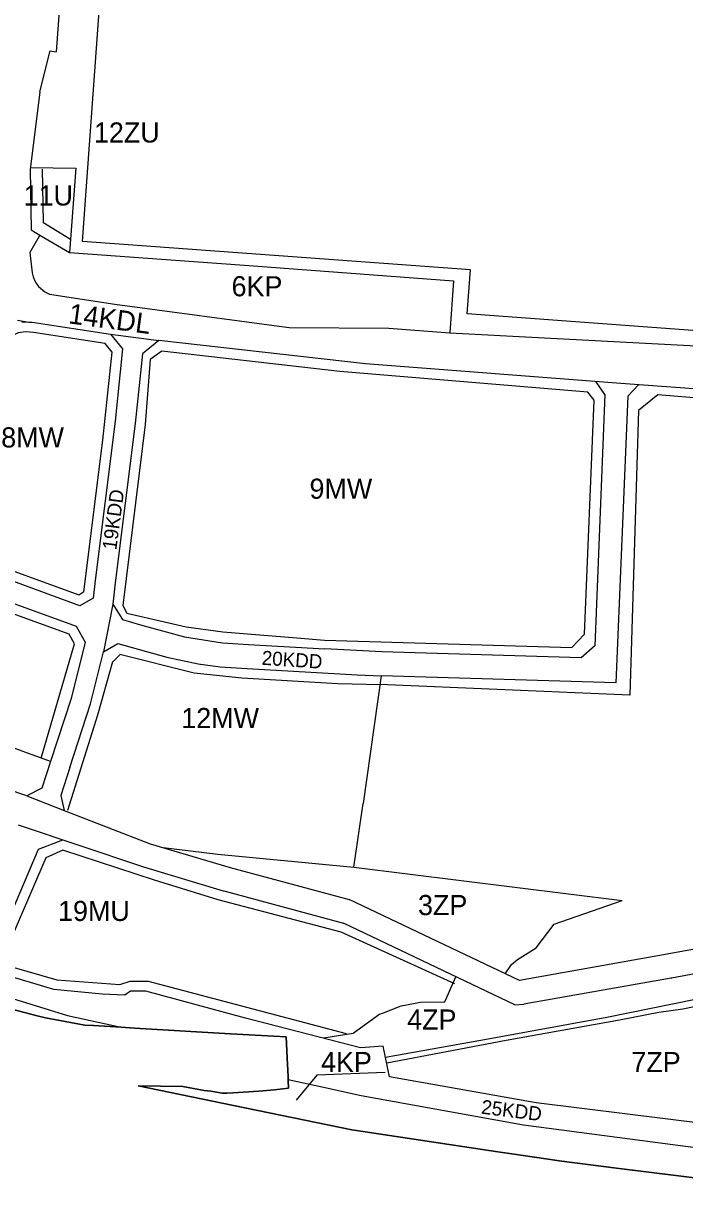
# Model space of a CAD drawing. Extents: x 7428203 to 7432868, y 5542672 to 5545406.
# Drawn here: x 7432004 to 7432333, y 5542818 to 5543396 of the extents above; entities that cross this region are included whole.
import ezdxf

# ---------------------------------------------------------------- set-up
doc = ezdxf.new("R2010")
doc.units = 0
for name, color, linetype in [('__LEGENDA_RAMKA_LOGO_PODZIAŁKA', 7, 'Continuous'), ('_GRANICA_MIASTA', 7, 'Continuous'), ('granicaBulwary', 7, 'Continuous'), ('MPZP_uchwalone_nieobowiazujace jeszcze_SZRAF', 7, 'Continuous')]:
    doc.layers.add(name, color=color, linetype=linetype)

msp = doc.modelspace()

# ---------------------------------------------------------------- linework, layer by layer
at = {"layer": '__LEGENDA_RAMKA_LOGO_PODZIAŁKA'}
msp.add_lwpolyline([(7431994.8, 5542906.65), (7432011.22, 5542902.36), (7432015.34, 5542901.29), (7432034.8, 5542897.77), (7432039.2, 5542897.51), (7432052.98, 5542896.69), (7432059.63, 5542896.3), (7432107.31, 5542893.48), (7432134.96, 5542891.84), (7432135.51, 5542881.51), (7432135.64, 5542878.11), (7432135.89, 5542872.37), (7432136, 5542870.15), (7432136.19, 5542866.32), (7432129.15, 5542865.52), (7432121.35, 5542864.94), (7432108.51, 5542864.06), (7432105.41, 5542863.84), (7432103.13, 5542863.99), (7432099.5, 5542864.5), (7432097.52, 5542864.92), (7432094.2, 5542865.19), (7432083.54, 5542867.28), (7432061.43, 5542867.58), (7432108.76, 5542857.84), (7432167.6, 5542845.74), (7432168.81, 5542845.49), (7432240.24, 5542834.78), (7432247.14, 5542833.74), (7432269.61, 5542830.37), (7432270.59, 5542830.22), (7432299.15, 5542826.68), (7432366.07, 5542818.36)], dxfattribs=at)
at = {"layer": '_GRANICA_MIASTA'}
for p, q in [((7432037.23, 5543621.26), (7432020.68, 5543381.69)), ((7432033.73, 5543287.48), (7432057.57, 5543619.82)), ((7432012.53, 5543361.9), (7432007.71, 5543323.27)), ((7432007.71, 5543323.27), (7432008.21, 5543293.28)), ((7432008.21, 5543293.28), (7432012.56, 5543290.59)), ((7432226.56, 5543273.31), (7432033.73, 5543287.48)), ((7432224.95, 5543251.39), (7432226.56, 5543273.31)), ((7432008.74, 5543271.82), (7432009.24, 5543269.81)), ((7432009.24, 5543269.81), (7432010.01, 5543267.87)), ((7432010.01, 5543267.87), (7432010.69, 5543266.65)), ((7432010.69, 5543266.65), (7432011.86, 5543265.07)), ((7432011.86, 5543265.07), (7432014.95, 5543262.4)), ((7432014.95, 5543262.4), (7432017.22, 5543261.23)), ((7432017.22, 5543261.23), (7432049.82, 5543256.21)), ((7432505.88, 5543230.9), (7432224.95, 5543251.39)), ((7432047.55, 5543241.39), (7432071.7, 5543238.19)), ((7432071.7, 5543238.19), (7432063.48, 5543231.48)), ((7432063.48, 5543231.48), (7432059.85, 5543196.95)), ((7432293.36, 5543211.37), (7432289.12, 5543217.69)), ((7432059.85, 5543196.95), (7432050.01, 5543117.61)), ((7432050.01, 5543117.61), (7432048.79, 5543107.04)), ((7432048.79, 5543107.04), (7432044.22, 5543083.37)), ((7432048.79, 5543107.04), (7432053.55, 5543099.39)), ((7432053.55, 5543099.39), (7432062.57, 5543096.75)), ((7432062.57, 5543096.75), (7432084.4, 5543090.89)), ((7432044.22, 5543083.37), (7432051.3, 5543087.55)), ((7432051.3, 5543087.55), (7432075.64, 5543080.66)), ((7432084.4, 5543090.89), (7432103.35, 5543087.86)), ((7432103.35, 5543087.86), (7432116.25, 5543087)), ((7432037.72, 5543057.46), (7432044.22, 5543083.37)), ((7432116.25, 5543087), (7432154.1, 5543084.92)), ((7432182.5, 5543083.35), (7432154.1, 5543084.92)), ((7432075.64, 5543080.66), (7432091.23, 5543077.48)), ((7432091.23, 5543077.48), (7432102.09, 5543075.91)), ((7432102.09, 5543075.91), (7432115.52, 5543075.02)), ((7432115.52, 5543075.02), (7432170.23, 5543072.01)), ((7432170.23, 5543072.01), (7432182.15, 5543071.36)), ((7432182.15, 5543071.36), (7432173.17, 5543007.95)), ((7432017.85, 5543028.79), (7431919, 5543064.95)), ((7432027.43, 5543025.93), (7432037.72, 5543057.46)), ((7432005.96, 5543011.7), (7432024.64, 5543004.41)), ((7432168.62, 5542976.37), (7432173.17, 5543007.95)), ((7432001.68, 5542997.32), (7432063.09, 5542976.74)), ((7432011.78, 5542985.25), (7432023.96, 5542989.85)), ((7431989.67, 5542933.23), (7432011.78, 5542985.25)), ((7432063.97, 5542976.44), (7432103.64, 5542964.58)), ((7432168.62, 5542976.37), (7432302.06, 5542959.76)), ((7432103.64, 5542964.58), (7432103.98, 5542964.48)), ((7432103.98, 5542964.48), (7432163.4, 5542948.38)), ((7432250.93, 5542919.95), (7432166.31, 5542960.28)), ((7432248.57, 5542907.78), (7432163.4, 5542948.38)), ((7432466.38, 5542946.5), (7432326.44, 5542921.16)), ((7432019.53, 5542915.43), (7431995.04, 5542922.73)), ((7432326.39, 5542921.15), (7432253.03, 5542908.13)), ((7432043.53, 5542913.22), (7432019.53, 5542915.43)), ((7432057.53, 5542914.56), (7432054.7, 5542912.58)), ((7432065.12, 5542914.7), (7432057.53, 5542914.56)), ((7432114.78, 5542901.27), (7432065.12, 5542914.7)), ((7432054.7, 5542912.58), (7432043.53, 5542913.22)), ((7432011.22, 5542902.36), (7431994.8, 5542906.65)), ((7432015.34, 5542901.29), (7432011.22, 5542902.36)), ((7432034.8, 5542897.77), (7432015.34, 5542901.29)), ((7432039.2, 5542897.51), (7432034.8, 5542897.77)), ((7432052.98, 5542896.69), (7432039.2, 5542897.51)), ((7432059.63, 5542896.3), (7432052.98, 5542896.69)), ((7432171.89, 5542886.38), (7432114.78, 5542901.27)), ((7432107.31, 5542893.48), (7432059.63, 5542896.3)), ((7432134.96, 5542891.84), (7432107.31, 5542893.48)), ((7432135.51, 5542881.51), (7432134.96, 5542891.84)), ((7432183.24, 5542887.35), (7432171.89, 5542886.38)), ((7432186.29, 5542871.95), (7432183.24, 5542887.35)), ((7432135.64, 5542878.11), (7432135.51, 5542881.51)), ((7432135.89, 5542872.37), (7432135.64, 5542878.11)), ((7432136, 5542870.15), (7432135.89, 5542872.37)), ((7432153.44, 5542866.78), (7432135.98, 5542870.54)), ((7432136.19, 5542866.32), (7432136, 5542870.15)), ((7432259.18, 5542859.04), (7432186.29, 5542871.95)), ((7432108.76, 5542857.84), (7432061.43, 5542867.58)), ((7432061.43, 5542867.58), (7432083.54, 5542867.28)), ((7432083.54, 5542867.28), (7432094.2, 5542865.19)), ((7432094.2, 5542865.19), (7432097.52, 5542864.92)), ((7432097.52, 5542864.92), (7432099.5, 5542864.5)), ((7432099.5, 5542864.5), (7432103.13, 5542863.99)), ((7432103.13, 5542863.99), (7432105.41, 5542863.84)), ((7432105.41, 5542863.84), (7432108.51, 5542864.06)), ((7432108.51, 5542864.06), (7432121.35, 5542864.94)), ((7432121.35, 5542864.94), (7432129.15, 5542865.52)), ((7432129.15, 5542865.52), (7432136.19, 5542866.32)), ((7432172.21, 5542862.58), (7432153.44, 5542866.78)), ((7432253.01, 5542848.01), (7432172.21, 5542862.58)), ((7432167.6, 5542845.74), (7432108.76, 5542857.84)), ((7432371.53, 5542845.19), (7432259.18, 5542859.04)), ((7432168.81, 5542845.49), (7432167.6, 5542845.74)), ((7432240.24, 5542834.78), (7432168.81, 5542845.49)), ((7432368.86, 5542832.71), (7432253.01, 5542848.01)), ((7432247.14, 5542833.74), (7432240.24, 5542834.78)), ((7432269.61, 5542830.37), (7432247.14, 5542833.74)), ((7432270.59, 5542830.22), (7432269.61, 5542830.37)), ((7432299.15, 5542826.68), (7432270.59, 5542830.22)), ((7432366.07, 5542818.36), (7432299.15, 5542826.68))]:
    msp.add_line(p, q, dxfattribs=at)
for points in [[(7432012.53, 5543361.9), (7432017.7, 5543382.28), (7432020.68, 5543381.69)], [(7432007.83, 5543324.19), (7432030.39, 5543323.92), (7432027.3, 5543281.94)], [(7432012.56, 5543290.59), (7432007.45, 5543281.86), (7432008.74, 5543271.82)], [(7432012.56, 5543290.59), (7432027.3, 5543281.94), (7432114.18, 5543275.56), (7432218.14, 5543267.92), (7432216.24, 5543242.02)], [(7432049.82, 5543256.21), (7432136.37, 5543244.64), (7432186.04, 5543244.35), (7432216.24, 5543242.02), (7432413.94, 5543231.48), (7432640.36, 5543214.85), (7432658.04, 5543210.49), (7432742.56, 5543204.3), (7432752.27, 5543212.93)], [(7432001.46, 5543248.23), (7432006.98, 5543247.37), (7432008.71, 5543247.29), (7432047.55, 5543241.39), (7432053.63, 5543234.02), (7432049.91, 5543198.06), (7432040.08, 5543118.81), (7432039.08, 5543110.11), (7432032.45, 5543106.16), (7431997.81, 5543118.94)], [(7432003.48, 5543247.42), (7432006.98, 5543247.37)], [(7432388.91, 5543210.14), (7432379.65, 5543211.02), (7432369.94, 5543211.73), (7432351.23, 5543213.11), (7432301.34, 5543216.75), (7432174.33, 5543226.52), (7432071.7, 5543238.19)], [(7432310.15, 5543216.11), (7432304.83, 5543210.52), (7432298.81, 5543067.88), (7432182.15, 5543071.36)], [(7432293.36, 5543211.37), (7432288.33, 5543086.28), (7432281.66, 5543080.39), (7432182.5, 5543083.35)], [(7431947.45, 5543143.42), (7431939.96, 5543122.74), (7431947.58, 5543126.31), (7432030.55, 5543096.2), (7432035.1, 5543088.13), (7432028.11, 5543060.23), (7432017.85, 5543028.79), (7432013.51, 5543015.49), (7432005.96, 5543011.7), (7431916.9, 5543041.85), (7431913.29, 5543049.4), (7431919, 5543064.95), (7431932.86, 5543102.67), (7431939.96, 5543122.74)], [(7432027.43, 5543025.93), (7432022.88, 5543011.96), (7432024.64, 5543004.41)], [(7432024.64, 5543004.41), (7432067.41, 5542987.94), (7432107.08, 5542976.08), (7432166.31, 5542960.28)], [(7432073.79, 5542986.03), (7432101.04, 5542982.71), (7432168.62, 5542976.37)], [(7432184.35, 5542881.75), (7432235.29, 5542890.99), (7432294.29, 5542901.7), (7432338.45, 5542910.71), (7432389.9, 5542920.66), (7432456.41, 5542933.52), (7432500.71, 5542941.8), (7432565.92, 5542953.99), (7432618.41, 5542964.35), (7432650.2, 5542970.62), (7432674.54, 5542974.93)], [(7432243.85, 5542923.32), (7432246.9, 5542927.86), (7432250.02, 5542930.35), (7432259.21, 5542936.21), (7432268.23, 5542947.98), (7432302.06, 5542959.76)], [(7432460.08, 5542957.66), (7432324.29, 5542932.96), (7432250.93, 5542919.95)], [(7432181.56, 5542903.12), (7432183.3, 5542903.84), (7432192.18, 5542907.3), (7432201.77, 5542909.09), (7432213.76, 5542909.39), (7432219.23, 5542921.76)], [(7432416.09, 5542923.14), (7432367.66, 5542913.04), (7432332.08, 5542905.7), (7432320.15, 5542904.09), (7432300.61, 5542900.16), (7432244.28, 5542890.06), (7432184.93, 5542878.81)], [(7431973.61, 5542918.72), (7432026.26, 5542902.45), (7432052.98, 5542896.69)], [(7432181.56, 5542903.12), (7432168.23, 5542893.61), (7432154.62, 5542891.46), (7432153.35, 5542891.21)], [(7432248.57, 5542907.78), (7432253.03, 5542908.13)]]:
    msp.add_lwpolyline(points, dxfattribs=at)
for centre, radius, start, end in [((7432067.21, 5542987.39), 11.42, 248.84231, 253.50827), ((7432326.4, 5542921.23), 0.0806, 262.87498, 299.74488)]:
    msp.add_arc(centre, radius, start, end, dxfattribs=at)
at = {"layer": 'granicaBulwary'}
msp.add_lwpolyline([(7432184.16, 5542874.26), (7432150.11, 5542872.87), (7432139.96, 5542860.39)], dxfattribs=at)
at = {"layer": 'MPZP_uchwalone_nieobowiazujace jeszcze_SZRAF'}
for p, q in [((7432013.71, 5543323.37), (7432014.15, 5543297)), ((7432048.55, 5543078.17), (7432052.39, 5543082.08)), ((7432089.14, 5543072.78), (7432052.3, 5543082.04)), ((7432048.58, 5543078.36), (7432041.14, 5543051.81)), ((7432112.85, 5543070.19), (7432089.14, 5543072.78)), ((7432160.69, 5543067.53), (7432112.85, 5543070.19)), ((7432181.81, 5543066.97), (7432160.69, 5543067.53)), ((7432041.14, 5543051.81), (7432026.29, 5543004.53))]:
    msp.add_line(p, q, dxfattribs=at)
for points in [[(7432014.04, 5543297.09), (7432027.79, 5543288.64)], [(7432034.39, 5543113.14), (7432043.73, 5543188.67), (7432048.44, 5543232.45), (7432044.91, 5543236.73), (7432009.4, 5543242.19), (7432005.32, 5543242.44), (7432001.75, 5543241.93), (7431999.15, 5543240.63), (7431997.6, 5543238.7), (7431987.79, 5543223.21), (7431977.48, 5543205.45), (7431967.63, 5543182.62), (7431959.31, 5543160.62), (7431953.35, 5543144.87), (7431955.89, 5543139.22), (7431979.8, 5543130.62), (7432031.84, 5543111.71), (7432034.42, 5543113.41)], [(7432411.3, 5543203.48), (7432319.63, 5543211.15), (7432310.08, 5543203.33), (7432305.74, 5543061.76), (7432181.54, 5543067.1)], [(7432013.15, 5543030.51), (7432029.77, 5543087.41), (7432027.1, 5543092.15), (7431947.8, 5543120.89), (7431943.97, 5543119.1), (7431923.69, 5543063.23)], [(7432023.88, 5542984.66), (7432015.52, 5542980.91), (7431995.17, 5542933.46), (7431998.58, 5542926.78), (7432020.96, 5542920.22), (7432052.26, 5542917.94), (7432057.44, 5542919.56), (7432066.42, 5542919.52), (7432164.7, 5542893.58)], [(7432218.86, 5542918.3), (7432162.21, 5542944.02), (7432101.13, 5542960.09), (7432069.56, 5542969.75), (7432023.88, 5542984.66)]]:
    msp.add_lwpolyline(points, dxfattribs=at)
msp.add_lwpolyline([(7432053.75, 5543106.47), (7432055.72, 5543102.67), (7432085.19, 5543095.83), (7432103.48, 5543093.3), (7432140.28, 5543090.36), (7432154.01, 5543089.22), (7432276.93, 5543085.54), (7432283.33, 5543092.2), (7432287.98, 5543208.54), (7432284.99, 5543212.49), (7432161.65, 5543222.82), (7432073.06, 5543232.83), (7432067.26, 5543228.78), (7432064.81, 5543196.33)], close=True, dxfattribs=at)

# ---------------------------------------------------------------- texts
at = {"layer": 'granicaBulwary'}
for s, p in [('12ZU', (7432039.39, 5543336.61)), ('11U', (7432004.43, 5543305.3)), ('6KP', (7432107.81, 5543260.16)), ('8MW', (7431993.29, 5543184.98)), ('9MW', (7432146.55, 5543159.49)), ('12MW', (7432082.81, 5543045.45)), ('3ZP', (7432200.49, 5542952.45)), ('19MU', (7432021.55, 5542949.53)), ('4ZP', (7432195.1, 5542895.52)), ('4KP', (7432152.29, 5542874.4)), ('7ZP', (7432306.55, 5542874.4))]:
    msp.add_text(s, height=10, dxfattribs=at).set_placement(p)
for s, height, rotation, p in [('14KDL', 10, 352.45262, (7432026.4, 5543246.74)), ('19KDD', 7, 82.44782, (7432050.49, 5543133.72)), ('20KDD', 7, 356.13563, (7432122.61, 5543076.97)), ('25KDD', 7, 352.81558, (7432231.64, 5542853.75))]:
    msp.add_text(s, height=height, rotation=rotation, dxfattribs=at).set_placement(p)

doc.saveas('drawing.dxf')
